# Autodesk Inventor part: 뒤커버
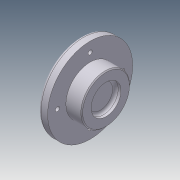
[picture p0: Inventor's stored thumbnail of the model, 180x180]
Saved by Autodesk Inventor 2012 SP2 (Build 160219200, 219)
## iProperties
Company: 한국ATC센터
Created: 2014-11
Part Number: 뒤커버
Document SubType Name: Modeling
Designer: KYOUNG IL JANG
Density: 2.71 g/cm^3
Material: 알루미늄-6061
Mass: 280.898 g
Surface Area: 198.677 cm^2
Volume: 103.653 cm^3
Author: KYOUNG IL JANG
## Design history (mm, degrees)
sketch "스케치1"
  geometry: L1 (-13.5, 0)-(13.5, 0); L2 (-13.5, 0)-(-13.5, 45.5); L3 (-13.5, 45.5)-(-3.5, 45.5); L4 (-3.5, 45.5)-(-3.5, 26); L5 (-3.5, 26)-(13.5, 26); L6 (13.5, 26)-(13.5, 0); 2 further points
  constraints: 12 end point, 3 parallel, 2 perpendicular, 1 coincident, 1 horizontal, 1 midpoint
  dimensions: "d0" = 27 distance of L1.start L1.end; "d1" = 91 diameter of L3 L1; "d2" = 52 diameter of L5 L1; "d3" = 10 distance of L2.end L3.end
revolve "회전1" sketch "스케치1" stored, may be unused: angle "d4" = 90 deg
sketch "스케치2"
  geometry: 2 further points
  constraints: 1 vertical alignment
  dimensions: "d14" = 35 distance of point (0, 0) point (0, 35)
hole "구멍2" sketch "스케치2" at (0, 35) diameter "d15" = 4.5; stored, may be unused: countersink angle "d19" = 90 deg, drill point angle "d21" = 118 deg; dims "d16" = 6, "d17" = 8, "d18" = 4.4, "d20" = 8
fillet "모깎기1" dims "d29" = 3
chamfer "모따기2" distance "d30" = 1; stored, may be unused: second distance "d31" = 2, angle "d32" = 30 deg
sketch "스케치3"
  geometry: L1 (-22.444, 6.652)-(-10, 14.967); L2 (-22.444, -6.652)-(-10, -14.967); L3 (10, -14.967)-(22.444, -6.652); L4 (22.444, 6.652)-(10, 14.967); A1 r 18 centre (0, 0) between (-18, 0) and (18, 0); A2 r 8 centre (18, 0) between (22.444, -6.652) and (22.444, 6.652); A3 r 8 centre (-18, 0) between (-22.444, 6.652) and (-22.444, -6.652); 1 further point
  constraints: 10 point on circle, 8 end point, 6 tangent, 3 centre point, 2 horizontal alignment, 2 parallel, 1 coincident, 1 equal radius
  dimensions: "d36" = 36 diameter of A1; "d37" = 16 diameter of A2
extrude "돌출1" join sketch "스케치3" distance "d38" = 7; taper "d39" = 0 deg
hole "구멍3" diameter "d43" = 32; stored, may be unused: countersink angle "d47" = 90 deg, drill point angle "d49" = 0 deg; dims "d41" = 10, "d42" = 10, "d44" = 6, "d45" = 4, "d46" = 2, "d48" = 6
fillet "모깎기2" dims "d40" = 3
node "솔리드1"
pattern_circular "원형 패턴2" dims angle "d34" = 360 deg
